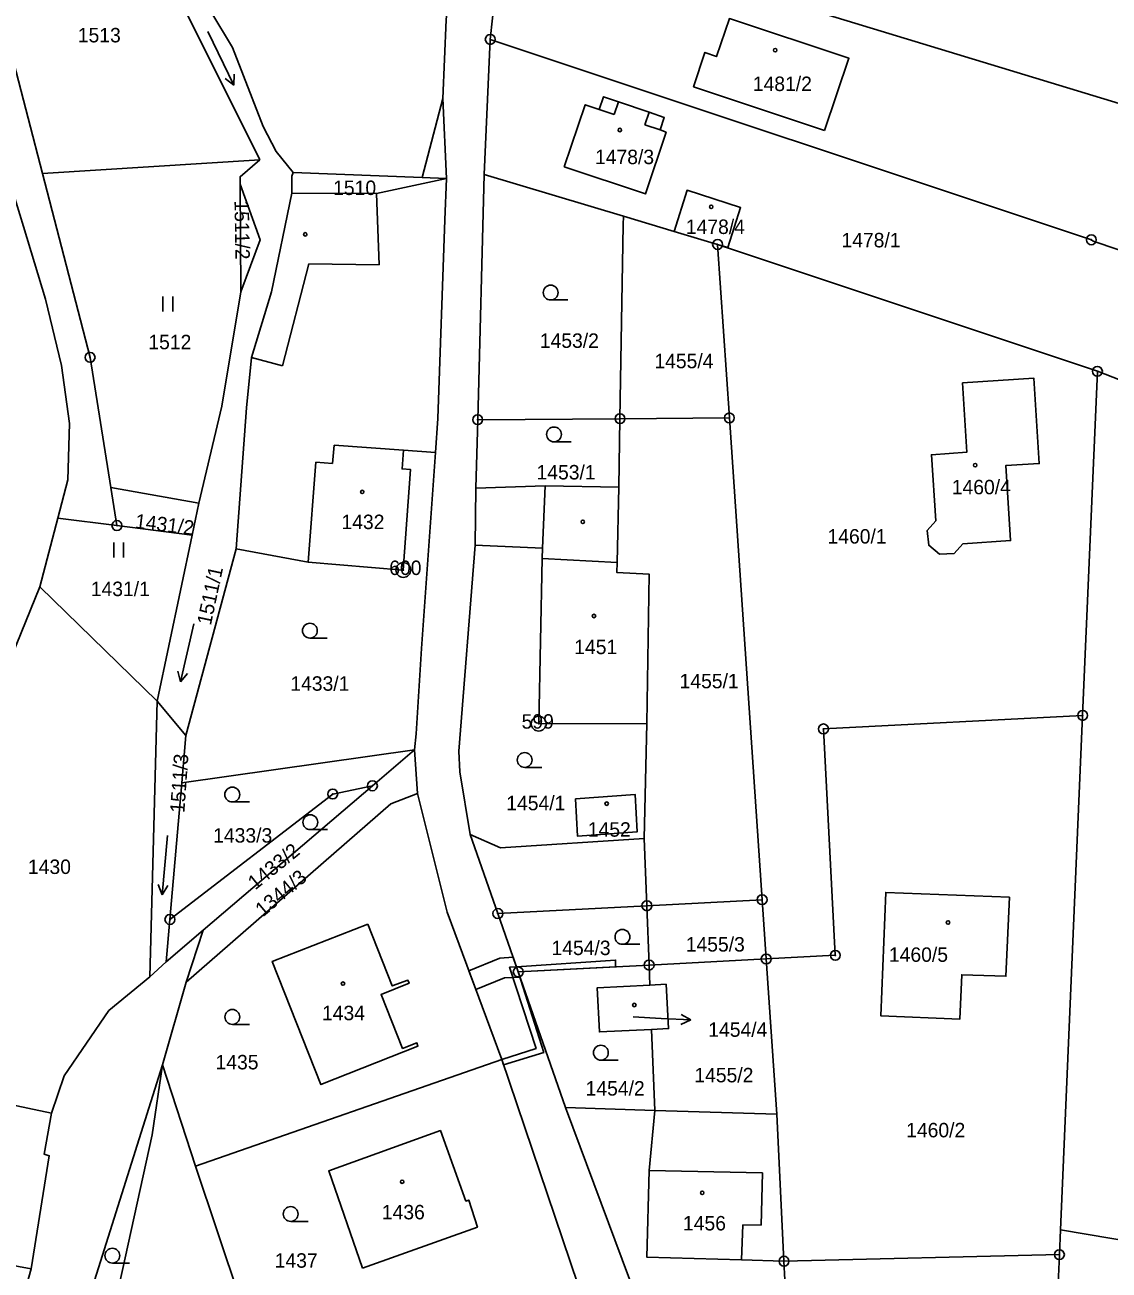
# Model space of a CAD drawing. Extents: x -587171 to -555306, y -1167727 to -1074732.
# Drawn here: x -559840.1 to -559730.5, y -1076086.1 to -1075960.2 of the extents above; entities that cross this region are included whole.
import ezdxf

# ---------------------------------------------------------------- set-up
doc = ezdxf.new("R2010")
doc.units = 0
for name, color, linetype in [('Hranice parcel', 7, 'Continuous'), ('Parcelní čísla', 7, 'Continuous'), ('Pop  PČ popisy', 7, 'Continuous'), ('Vnitřní kresba', 7, 'Continuous'), ('Věcná břemena k části', 7, 'Continuous'), ('Značky bodu BP', 7, 'Continuous'), ('Značky budov', 7, 'Continuous'), ('Značky kultur', 7, 'Continuous')]:
    doc.layers.add(name, color=color, linetype=linetype)

msp = doc.modelspace()

# ---------------------------------------------------------------- linework, layer by layer
at = {"layer": 'Hranice parcel'}
for p, q in [((-559793.07, -1075961.71), (-559791.7, -1075949.26)), ((-559793.7, -1075975.36), (-559793.07, -1075961.71)), ((-559816.35, -1075973.89), (-559838.34, -1075975.26)), ((-559794.34, -1076000.15), (-559793.7, -1075975.36)), ((-559793.7, -1075975.36), (-559779.6, -1075979.59)), ((-559818.28, -1075987.24), (-559818.35, -1075976.36)), ((-559779.6, -1075979.59), (-559774.47, -1075981.13)), ((-559774.47, -1075981.13), (-559770.09, -1075982.44)), ((-559770.09, -1075982.44), (-559768.9, -1075999.97)), ((-559770.09, -1075982.44), (-559731.7, -1075995.26)), ((-559731.7, -1075995.26), (-559733.19, -1076030.04)), ((-559718.16, -1076000.48), (-559731.7, -1075995.26)), ((-559794.52, -1076007.06), (-559794.34, -1076000.15)), ((-559779.96, -1076000.05), (-559794.34, -1076000.15)), ((-559779.96, -1076000.05), (-559780.08, -1076006.97)), ((-559768.9, -1075999.97), (-559779.96, -1076000.05)), ((-559765.59, -1076048.67), (-559768.9, -1075999.97)), ((-559836.78, -1076010.09), (-559835.76, -1076006.22)), ((-559822.53, -1076008.59), (-559831.42, -1076007)), ((-559831.42, -1076007), (-559830.81, -1076010.85)), ((-559794.58, -1076012.84), (-559794.52, -1076007.06)), ((-559823.21, -1076011.82), (-559822.53, -1076008.59)), ((-559836.78, -1076010.09), (-559838.6, -1076017.03)), ((-559830.81, -1076010.85), (-559836.78, -1076010.09)), ((-559823.21, -1076011.82), (-559830.81, -1076010.85)), ((-559826.73, -1076028.59), (-559823.21, -1076011.82)), ((-559818.76, -1076013.19), (-559823.85, -1076032.08)), ((-559826.73, -1076028.59), (-559838.6, -1076017.03)), ((-559827.47, -1076056.48), (-559826.73, -1076028.59)), ((-559823.85, -1076032.08), (-559826.73, -1076028.59)), ((-559733.19, -1076030.04), (-559735.43, -1076082.03)), ((-559823.85, -1076032.08), (-559824.26, -1076036.85)), ((-559824.26, -1076036.85), (-559800.72, -1076033.53)), ((-559804.98, -1076037.16), (-559800.72, -1076033.53)), ((-559800.72, -1076033.53), (-559800.41, -1076037.93)), ((-559825.45, -1076050.67), (-559824.26, -1076036.85)), ((-559822.08, -1076051.75), (-559804.98, -1076037.16)), ((-559777.24, -1076049.28), (-559765.59, -1076048.67)), ((-559765.18, -1076054.66), (-559765.59, -1076048.67)), ((-559792.3, -1076050.07), (-559777.24, -1076049.28)), ((-559790.24, -1076055.97), (-559792.3, -1076050.07)), ((-559777.01, -1076055.28), (-559777.24, -1076049.28)), ((-559825.45, -1076050.67), (-559825.82, -1076054.94)), ((-559825.82, -1076054.94), (-559822.08, -1076051.75)), ((-559823.8, -1076057.02), (-559822.08, -1076051.75)), ((-559827.47, -1076056.48), (-559825.82, -1076054.94)), ((-559777.01, -1076055.28), (-559790.24, -1076055.97)), ((-559765.18, -1076054.66), (-559777.01, -1076055.28)), ((-559776.93, -1076057.3), (-559777.01, -1076055.28)), ((-559764.11, -1076070.35), (-559765.18, -1076054.66)), ((-559785.45, -1076069.69), (-559790.24, -1076055.97)), ((-559823.8, -1076057.02), (-559826.2, -1076065.36)), ((-559776.45, -1076069.97), (-559776.76, -1076061.78)), ((-559834.85, -1076092.79), (-559826.2, -1076065.36)), ((-559826.2, -1076065.36), (-559822.86, -1076075.59)), ((-559822.86, -1076075.59), (-559791.91, -1076064.81)), ((-559784.21, -1076087.54), (-559791.91, -1076064.81)), ((-559785.45, -1076069.69), (-559776.45, -1076069.97)), ((-559764.11, -1076070.35), (-559776.45, -1076069.97)), ((-559763.38, -1076085.21), (-559764.11, -1076070.35)), ((-559822.86, -1076075.59), (-559815.22, -1076098.33)), ((-559735.43, -1076082.03), (-559735.54, -1076084.55)), ((-559735.43, -1076082.03), (-559715.32, -1076085.46)), ((-559763.38, -1076085.21), (-559735.54, -1076084.55)), ((-559763.38, -1076085.21), (-559762.91, -1076094.66)), ((-559735.54, -1076084.55), (-559735.95, -1076094.02)), ((-559845.7, -1076108.53), (-559839.49, -1076085.97))]:
    msp.add_line(p, q, dxfattribs=at)
for points in [[(-559835.76, -1076006.22), (-559835.59, -1076000.52), (-559836.4, -1075994.67), (-559838.02, -1075987.96), (-559840.25, -1075980.63), (-559841.73, -1075975.77), (-559844.21, -1075964.76), (-559848.13, -1075955.08), (-559852.29, -1075950.24), (-559858.29, -1075945.41), (-559862.88, -1075939.48), (-559868.76, -1075929.64), (-559874.12, -1075919.11), (-559878.44, -1075904.13), (-559879.85, -1075884.48)], [(-559827.53, -1075928.29), (-559827.39, -1075939.43), (-559826.78, -1075947.01), (-559823.49, -1075955.23), (-559819.12, -1075962.54), (-559816.01, -1075970.51), (-559814.71, -1075973.03), (-559813, -1075975.17)], [(-559816.35, -1075973.89), (-559825.13, -1075956.31), (-559829.35, -1075947.86), (-559830.22, -1075935.86)], [(-559794.56, -1075939.26), (-559796.78, -1075951.74), (-559797.54, -1075959.73), (-559797.88, -1075967.67), (-559797.5, -1075975.77)], [(-559838.34, -1075975.26), (-559841.24, -1075964.07), (-559845.75, -1075952.87), (-559849.83, -1075948.61)], [(-559791.7, -1075949.26), (-559719.97, -1075971.09), (-559700.9, -1075977.11), (-559674.04, -1075985.69)], [(-559759.3, -1075970.93), (-559772.52, -1075966.5), (-559771.38, -1075963.03), (-559770.21, -1075963.45), (-559768.9, -1075959.6), (-559756.81, -1075963.62), (-559759.3, -1075970.93)], [(-559717.48, -1075987.07), (-559732.13, -1075982.11), (-559732.31, -1075981.97), (-559793.07, -1075961.71)], [(-559785.6, -1075974.58), (-559783.47, -1075968.32), (-559782.05, -1075968.79), (-559781.62, -1075967.51), (-559780.1, -1075968.03), (-559777.01, -1075969.07), (-559775.48, -1075969.59), (-559775.91, -1075970.86), (-559775.3, -1075971.1), (-559777.39, -1075977.33), (-559785.6, -1075974.58)], [(-559818.35, -1075976.36), (-559818.36, -1075975.59), (-559816.35, -1075973.89)], [(-559831.42, -1076007), (-559833.52, -1075993.85), (-559838.34, -1075975.26)], [(-559813, -1075975.17), (-559813.13, -1075975.55), (-559813.13, -1075977.26)], [(-559797.5, -1075975.77), (-559804.57, -1075977.29), (-559813.13, -1075977.26)], [(-559813, -1075975.17), (-559799.96, -1075975.67), (-559797.5, -1075975.77)], [(-559798.62, -1076003.46), (-559798.38, -1076000.04), (-559797.66, -1075979.95), (-559797.5, -1075975.77)], [(-559813.13, -1075977.26), (-559815.17, -1075987.22), (-559817.19, -1075993.88), (-559817.7, -1075998.96), (-559818.76, -1076013.19)], [(-559818.35, -1075976.36), (-559816.32, -1075981.96), (-559818.28, -1075987.24)], [(-559774.47, -1075981.13), (-559773.17, -1075976.96), (-559767.77, -1075978.71), (-559769.05, -1075982.76), (-559770.09, -1075982.44)], [(-559779.96, -1076000.05), (-559779.62, -1075980.45), (-559779.6, -1075979.59)], [(-559822.53, -1076008.59), (-559820.2, -1075998.77), (-559818.28, -1075987.24)], [(-559745.34, -1075996.41), (-559738.13, -1075995.94), (-559737.57, -1076004.59), (-559740.96, -1076004.79), (-559740.47, -1076012.37), (-559745.31, -1076012.7), (-559746.18, -1076013.66), (-559747.66, -1076013.76), (-559748.75, -1076012.85), (-559748.9, -1076011.36), (-559748.04, -1076010.38), (-559748.48, -1076003.69), (-559744.9, -1076003.44), (-559745.34, -1075996.41)], [(-559818.76, -1076013.19), (-559811.49, -1076014.54), (-559801.86, -1076015.35), (-559801.13, -1076005.19), (-559801.98, -1076005.12), (-559801.83, -1076003.23), (-559798.62, -1076003.46)], [(-559800.72, -1076033.53), (-559800.56, -1076031.89), (-559800.01, -1076023.27), (-559798.62, -1076003.46)], [(-559780.08, -1076006.97), (-559787.52, -1076006.84), (-559794.52, -1076007.06)], [(-559777.23, -1076030.86), (-559777, -1076015.77), (-559780.27, -1076015.61), (-559780.24, -1076014.57), (-559780.08, -1076006.97)], [(-559792.3, -1076050.07), (-559795.09, -1076042.09), (-559796.13, -1076035.76), (-559796.24, -1076033.66), (-559794.58, -1076012.84)], [(-559794.58, -1076012.84), (-559787.79, -1076013.13), (-559787.83, -1076014.18), (-559788.17, -1076030.88), (-559777.23, -1076030.86)], [(-559838.6, -1076017.03), (-559841.43, -1076024.02), (-559848.7, -1076037.16), (-559855.44, -1076060.45)], [(-559765.18, -1076054.66), (-559758.19, -1076054.29), (-559759.39, -1076031.41), (-559733.19, -1076030.04)], [(-559777.24, -1076049.28), (-559777.5, -1076042.47), (-559777.23, -1076030.86)], [(-559804.98, -1076037.16), (-559808.99, -1076037.99), (-559825.45, -1076050.67)], [(-559800.41, -1076037.93), (-559803.12, -1076038.98), (-559823.8, -1076057.02)], [(-559791.91, -1076064.81), (-559797.43, -1076049.92), (-559800.41, -1076037.93)], [(-559784.45, -1076038.48), (-559784.25, -1076042.25), (-559778.21, -1076041.81), (-559778.41, -1076038.05), (-559784.45, -1076038.48)], [(-559740.6, -1076048.43), (-559740.95, -1076056.41), (-559745.41, -1076056.25), (-559745.59, -1076060.73), (-559753.58, -1076060.41), (-559753.09, -1076047.93), (-559740.6, -1076048.43)], [(-559805.46, -1076051.15), (-559815.11, -1076054.91), (-559810.19, -1076067.35), (-559800.38, -1076063.48), (-559800.49, -1076063.14), (-559801.94, -1076063.71), (-559804.1, -1076058.24), (-559801.28, -1076057.12), (-559801.4, -1076056.81), (-559802.98, -1076057.39), (-559805.46, -1076051.15)], [(-559837.41, -1076070.24), (-559836.15, -1076066.46), (-559831.62, -1076059.87), (-559827.47, -1076056.48)], [(-559776.76, -1076061.78), (-559782.03, -1076062.04), (-559782.25, -1076057.57), (-559776.93, -1076057.3)], [(-559776.93, -1076057.3), (-559775.29, -1076057.22), (-559775.05, -1076061.69), (-559776.76, -1076061.78)], [(-559837.41, -1076070.24), (-559850.71, -1076067.45), (-559849.43, -1076061.53), (-559855.44, -1076060.45)], [(-559826.2, -1076065.36), (-559827.24, -1076072.43), (-559833, -1076098.69), (-559837.24, -1076103.11)], [(-559839.49, -1076085.97), (-559837.64, -1076074.56), (-559838.16, -1076074.4), (-559837.41, -1076070.24)], [(-559761.69, -1076119.01), (-559765.87, -1076111.68), (-559775.38, -1076094.3), (-559778.98, -1076087.02), (-559785.45, -1076069.69)], [(-559776.45, -1076069.97), (-559777.02, -1076076.05), (-559777.25, -1076084.79), (-559767.68, -1076085.08), (-559763.38, -1076085.21)], [(-559806, -1076085.9), (-559794.37, -1076081.76), (-559795.25, -1076079.04), (-559795.53, -1076079.13), (-559798.11, -1076072.01), (-559809.39, -1076076.09), (-559806, -1076085.9)]]:
    msp.add_lwpolyline(points, dxfattribs=at)
at = {"layer": 'Pop  PČ popisy'}
for p, q in [((-559778.61, -1076060.51), (-559775.79, -1076060.67)), ((-559772.79, -1076060.83), (-559773.77, -1076060.27)), ((-559775.79, -1076060.67), (-559772.79, -1076060.83)), ((-559772.79, -1076060.83), (-559773.82, -1076061.27))]:
    msp.add_line(p, q, dxfattribs=at)
at = {"layer": 'Vnitřní kresba'}
for p, q in [((-559797.88, -1075967.67), (-559799.96, -1075975.67)), ((-559780.53, -1075969.3), (-559780.1, -1075968.03)), ((-559782.05, -1075968.79), (-559780.53, -1075969.3)), ((-559777.01, -1075969.07), (-559777.44, -1075970.35)), ((-559777.44, -1075970.35), (-559775.91, -1075970.86)), ((-559804.31, -1075984.49), (-559804.57, -1075977.29)), ((-559814.06, -1075994.69), (-559811.4, -1075984.4)), ((-559811.4, -1075984.4), (-559804.31, -1075984.49)), ((-559817.19, -1075993.88), (-559814.06, -1075994.69)), ((-559808.86, -1076002.71), (-559809.02, -1076004.57)), ((-559801.83, -1076003.23), (-559808.86, -1076002.71)), ((-559810.71, -1076004.44), (-559811.49, -1076014.54)), ((-559809.02, -1076004.57), (-559810.71, -1076004.44)), ((-559787.79, -1076013.13), (-559787.52, -1076006.84)), ((-559780.24, -1076014.57), (-559787.83, -1076014.18)), ((-559795.09, -1076042.09), (-559792.02, -1076043.42)), ((-559792.02, -1076043.42), (-559777.5, -1076042.47)), ((-559765.54, -1076076.28), (-559777.02, -1076076.05)), ((-559765.69, -1076081.58), (-559765.54, -1076076.28)), ((-559767.68, -1076085.08), (-559767.54, -1076081.53)), ((-559767.54, -1076081.53), (-559765.69, -1076081.58)), ((-559859.56, -1076082.28), (-559839.49, -1076085.97))]:
    msp.add_line(p, q, dxfattribs=at)
at = {"layer": 'Věcná břemena k části'}
for points in [[(-559794.53, -1076057.75), (-559791.62, -1076056.58), (-559790.05, -1076056.51), (-559790.24, -1076055.97), (-559790.76, -1076054.47), (-559792.1, -1076054.58), (-559795.23, -1076055.85)], [(-559791.91, -1076064.81), (-559791.72, -1076065.37), (-559787.67, -1076064.1), (-559790.24, -1076055.97), (-559790.42, -1076055.45), (-559791.12, -1076055.5), (-559788.43, -1076063.71)], [(-559790.42, -1076055.45), (-559790.24, -1076055.97), (-559780.42, -1076055.46), (-559780.4, -1076054.78)]]:
    msp.add_lwpolyline(points, close=True, dxfattribs=at)
at = {"layer": 'Značky bodu BP'}
for centre, radius in [((-559793.07, -1075961.71), 0.5), ((-559793.07, -1075961.71), 0.0303), ((-559770.09, -1075982.44), 0.5), ((-559770.09, -1075982.44), 0.0303), ((-559732.31, -1075981.97), 0.5), ((-559732.31, -1075981.97), 0.0303), ((-559833.52, -1075993.85), 0.5), ((-559833.52, -1075993.85), 0.0303), ((-559731.7, -1075995.26), 0.5), ((-559731.7, -1075995.26), 0.0303), ((-559794.34, -1076000.15), 0.5), ((-559794.34, -1076000.15), 0.0303), ((-559779.96, -1076000.05), 0.5), ((-559779.96, -1076000.05), 0.0303), ((-559768.9, -1075999.97), 0.5), ((-559768.9, -1075999.97), 0.0303), ((-559830.81, -1076010.85), 0.5), ((-559830.81, -1076010.85), 0.0303), ((-559801.86, -1076015.35), 0.75), ((-559801.86, -1076015.35), 0.03), ((-559788.17, -1076030.88), 0.75), ((-559733.19, -1076030.04), 0.5), ((-559733.19, -1076030.04), 0.0303), ((-559788.17, -1076030.88), 0.03), ((-559759.39, -1076031.41), 0.5), ((-559759.39, -1076031.41), 0.0303), ((-559804.98, -1076037.16), 0.5), ((-559808.99, -1076037.99), 0.5), ((-559804.98, -1076037.16), 0.0303), ((-559808.99, -1076037.99), 0.0303), ((-559777.24, -1076049.28), 0.5), ((-559777.24, -1076049.28), 0.0303), ((-559765.59, -1076048.67), 0.5), ((-559765.59, -1076048.67), 0.0303), ((-559825.45, -1076050.67), 0.5), ((-559792.3, -1076050.07), 0.5), ((-559792.3, -1076050.07), 0.0303), ((-559825.45, -1076050.67), 0.0303), ((-559765.18, -1076054.66), 0.5), ((-559758.19, -1076054.29), 0.5), ((-559758.19, -1076054.29), 0.0303), ((-559790.24, -1076055.97), 0.5), ((-559777.01, -1076055.28), 0.5), ((-559777.01, -1076055.28), 0.0303), ((-559765.18, -1076054.66), 0.0303), ((-559790.24, -1076055.97), 0.0303), ((-559735.54, -1076084.55), 0.5), ((-559763.38, -1076085.21), 0.5), ((-559763.38, -1076085.21), 0.0303), ((-559735.54, -1076084.55), 0.0303)]:
    msp.add_circle(centre, radius, dxfattribs=at)
at = {"layer": 'Značky budov'}
for centre in [(-559764.27, -1075962.8), (-559779.97, -1075970.87), (-559770.73, -1075978.63), (-559811.77, -1075981.42), (-559744.05, -1076004.75), (-559806.01, -1076007.45), (-559783.72, -1076010.47), (-559782.59, -1076019.99), (-559781.3, -1076038.96), (-559746.8, -1076050.98), (-559807.96, -1076057.15), (-559778.51, -1076059.32), (-559801.98, -1076077.18), (-559771.64, -1076078.3)]:
    msp.add_circle(centre, 0.175, dxfattribs=at)
at = {"layer": 'Značky kultur'}
for p, q in [((-559821.61, -1075960.92), (-559818.98, -1075966.32)), ((-559818.98, -1075966.32), (-559819.86, -1075965.66)), ((-559818.98, -1075966.32), (-559818.96, -1075965.22)), ((-559826.15, -1075989.21), (-559826.15, -1075987.71)), ((-559825.15, -1075989.21), (-559825.15, -1075987.71)), ((-559786.97, -1075988.05), (-559785.22, -1075988.05)), ((-559786.63, -1076002.39), (-559784.88, -1076002.39)), ((-559831.13, -1076014.07), (-559831.13, -1076012.57)), ((-559830.13, -1076014.07), (-559830.13, -1076012.57)), ((-559823.04, -1076020.79), (-559824.39, -1076026.64)), ((-559811.3, -1076022.23), (-559809.55, -1076022.23)), ((-559824.39, -1076026.64), (-559824.66, -1076025.57)), ((-559824.39, -1076026.64), (-559823.68, -1076025.8)), ((-559789.59, -1076035.3), (-559787.84, -1076035.3)), ((-559819.15, -1076038.79), (-559817.4, -1076038.79)), ((-559811.26, -1076041.59), (-559809.51, -1076041.59)), ((-559825.71, -1076042.19), (-559826.23, -1076048.17)), ((-559826.23, -1076048.17), (-559826.65, -1076047.15)), ((-559826.23, -1076048.17), (-559825.65, -1076047.24)), ((-559779.71, -1076053.18), (-559777.96, -1076053.18)), ((-559819.14, -1076061.27), (-559817.39, -1076061.27)), ((-559781.89, -1076064.89), (-559780.14, -1076064.89)), ((-559813.24, -1076081.19), (-559811.49, -1076081.19)), ((-559831.27, -1076085.4), (-559829.52, -1076085.4))]:
    msp.add_line(p, q, dxfattribs=at)
for centre in [(-559786.97, -1075987.3), (-559786.63, -1076001.64), (-559811.3, -1076021.48), (-559789.59, -1076034.55), (-559819.15, -1076038.04), (-559811.26, -1076040.84), (-559779.71, -1076052.43), (-559819.14, -1076060.52), (-559781.89, -1076064.14), (-559813.24, -1076080.44), (-559831.27, -1076084.65)]:
    msp.add_circle(centre, 0.75, dxfattribs=at)

# ---------------------------------------------------------------- texts
at = {"layer": 'Parcelní čísla'}
for s, p in [('1513', (-559834.76, -1075962.01)), ('1481/2', (-559766.53, -1075966.93)), ('1478/3', (-559782.48, -1075974.32)), ('1510', (-559808.95, -1075977.44)), ('1478/4', (-559773.3, -1075981.38)), ('1478/1', (-559757.57, -1075982.73)), ('1453/2', (-559788.06, -1075992.89)), ('1512', (-559827.63, -1075993.03)), ('1455/4', (-559776.48, -1075994.95)), ('1453/1', (-559788.39, -1076006.19)), ('1460/4', (-559746.42, -1076007.69)), ('1432', (-559808.11, -1076011.21)), ('1460/1', (-559758.98, -1076012.67)), ('1431/1', (-559833.45, -1076017.98)), ('1451', (-559784.58, -1076023.85)), ('1433/1', (-559813.28, -1076027.55)), ('1455/1', (-559773.93, -1076027.3)), ('1454/1', (-559791.45, -1076039.63)), ('1433/3', (-559821.08, -1076042.9)), ('1452', (-559783.21, -1076042.3)), ('1430', (-559839.8, -1076046.07)), ('1454/3', (-559786.88, -1076054.27)), ('1455/3', (-559773.31, -1076053.91)), ('1460/5', (-559752.77, -1076054.95)), ('1434', (-559810.08, -1076060.85)), ('1454/4', (-559771.03, -1076062.53)), ('1435', (-559820.84, -1076065.82)), ('1455/2', (-559772.44, -1076067.13)), ('1454/2', (-559783.43, -1076068.47)), ('1460/2', (-559751.03, -1076072.69)), ('1436', (-559804.03, -1076080.98)), ('1456', (-559773.59, -1076082.1)), ('1437', (-559814.86, -1076085.87))]:
    msp.add_text(s, height=1.46, dxfattribs=at).set_placement(p)
for s, rotation, p in [('1511/2', 271, (-559818.93, -1075978)), ('1431/2', 353, (-559829.03, -1076011.1)), ('1511/1', 78, (-559821.31, -1076021)), ('1511/3', 86, (-559823.99, -1076039.93)), ('1433/2', 39, (-559816.83, -1076047.74)), ('1344/3', 40, (-559816.06, -1076050.47))]:
    msp.add_text(s, height=1.46, rotation=rotation, dxfattribs=at).set_placement(p)
at = {"layer": 'Značky bodu BP'}
for s, p in [('600', (-559803.28, -1076015.85)), ('599', (-559789.9, -1076031.38))]:
    msp.add_text(s, height=1.46, dxfattribs=at).set_placement(p)

doc.saveas('drawing.dxf')
